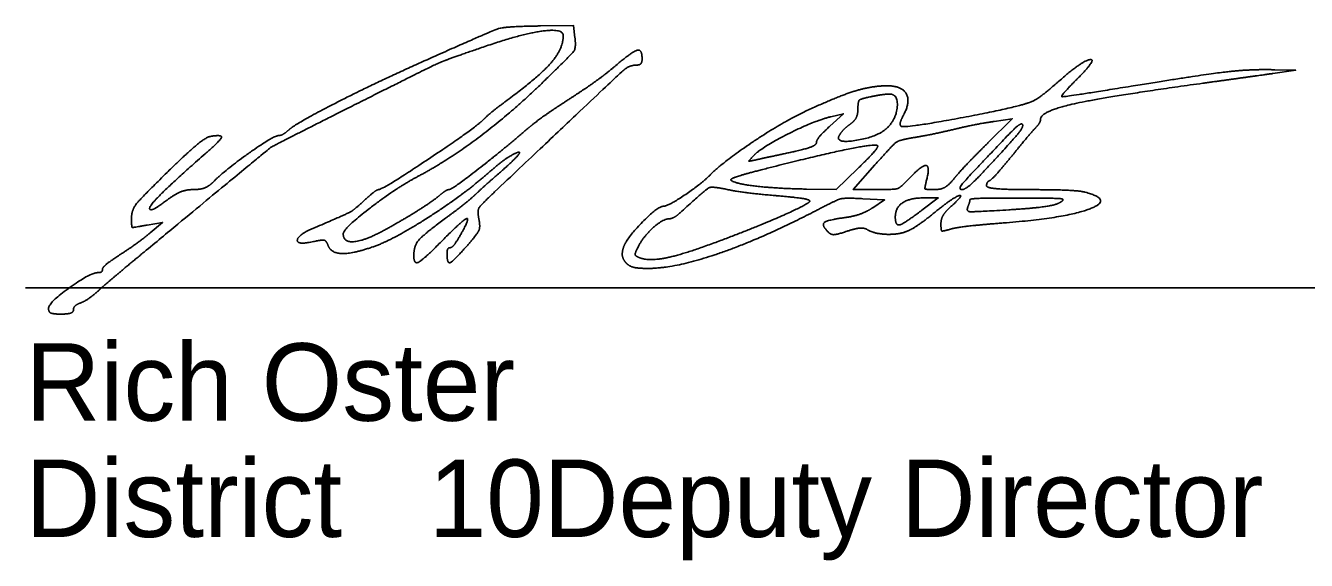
# Model space of a CAD drawing. Extents: x 6.3 to 40.3, y 9 to 31.
# Drawn here: x 30.872 to 33.187, y 17.168 to 18.134 of the extents above; entities that cross this region are included whole.
import ezdxf

# ---------------------------------------------------------------- set-up
doc = ezdxf.new("R2010")
doc.units = 0
doc.layers.add('SH_Data', color=7, linetype='Continuous')
doc.layers.add('SH_Text', color=7, linetype='Continuous')

msp = doc.modelspace()

# ---------------------------------------------------------------- linework, layer by layer
at = {"layer": 'SH_Data'}
msp.add_line((30.8725, 17.66), (34.3725, 17.66), dxfattribs=at)
at = {"layer": 'SH_Text'}
msp.add_line((30.9139, 17.6229), (30.9139, 17.6229), dxfattribs=at)
for points in [[(31.8651, 18.1121), (31.8626, 18.1339), (31.8026, 18.1333)], [(33.1264, 18.0474), (33.1676, 18.0532), (33.1299, 18.0542)], [(32.3277, 17.9693), (32.3501, 17.9746), (32.3258, 17.9524)], [(32.6227, 17.9608), (32.6553, 17.9656), (32.6114, 17.9222)], [(32.3762, 17.8757), (32.337, 17.8377), (32.2836, 17.8386)], [(32.4089, 17.8377), (32.368, 17.8377), (32.4072, 17.8822)], [(32.3855, 17.8212), (32.4247, 17.8189), (32.4033, 17.8049)], [(32.4964, 17.8227), (32.5216, 17.8227), (32.4921, 17.8004)], [(31.092, 17.7735), (31.1201, 17.7784), (31.0976, 17.7596)]]:
    msp.add_lwpolyline(points, dxfattribs=at)
for points in [[(31.8026, 18.1333), (31.7402, 18.1326), (31.7137, 18.1243), (31.5776, 18.0632)], [(31.7051, 18.0972), (31.7692, 18.1191), (31.8439, 18.1291), (31.8439, 18.1158)], [(31.8439, 18.1158), (31.8439, 18.0918), (31.7989, 18.0404), (31.7397, 17.9969)], [(31.8051, 18.0296), (31.8591, 18.082), (31.8673, 18.0933), (31.8651, 18.1121)], [(31.4951, 18.0049), (31.6073, 18.0613), (31.6329, 18.0725), (31.7051, 18.0972)], [(31.9864, 18.0739), (31.9864, 18.0919), (31.9688, 18.0871), (31.9371, 18.0603)], [(31.5776, 18.0632), (31.4974, 18.0272), (31.3616, 17.9576), (31.3483, 17.9457)], [(31.72, 17.8335), (31.9414, 18.0431), (31.9634, 18.0627), (31.977, 18.0627)], [(31.9371, 18.0603), (31.9209, 18.0465), (31.884, 18.0201), (31.8551, 18.0014)], [(31.977, 18.0627), (31.9822, 18.0627), (31.9864, 18.0677), (31.9864, 18.0739)], [(32.7732, 18.0383), (32.81, 18.0751), (32.7805, 18.0698), (32.7375, 18.0318)], [(33.1299, 18.0542), (33.0855, 18.0554), (33.0016, 18.0457), (32.8699, 18.0244)], [(31.5818, 17.8617), (31.6355, 17.8901), (31.7502, 17.9763), (31.8051, 18.0296)], [(32.7375, 18.0318), (32.7183, 18.0149), (32.6959, 17.9985), (32.6876, 17.9955)], [(32.7064, 17.9648), (32.7064, 17.9792), (32.829, 18.0064), (32.9997, 18.0298)], [(32.8699, 18.0244), (32.7495, 18.0048), (32.7409, 18.0061), (32.7732, 18.0383)], [(32.9997, 18.0298), (33.0467, 18.0363), (33.1037, 18.0442), (33.1264, 18.0474)], [(31.0864, 17.7247), (31.311, 17.9107), (31.3205, 17.9173), (31.4951, 18.0049)], [(32.429, 18.0252), (32.4015, 18.0252), (32.3397, 18.006), (32.2842, 17.9804)], [(32.3764, 17.9834), (32.3764, 17.9969), (32.3817, 18.0019), (32.3998, 18.0055)], [(32.3998, 18.0055), (32.4127, 18.0081), (32.4279, 18.0102), (32.4336, 18.0102)], [(32.4591, 17.973), (32.4718, 17.9969), (32.4555, 18.0252), (32.429, 18.0252)], [(32.4336, 18.0102), (32.4486, 18.0102), (32.4466, 17.9674), (32.4308, 17.9507)], [(31.7397, 17.9969), (31.7248, 17.986), (31.7067, 17.9711), (31.6994, 17.9638)], [(31.8551, 18.0014), (31.8263, 17.9828), (31.7925, 17.9588), (31.7801, 17.9482)], [(32.3628, 17.9562), (32.3703, 17.9616), (32.3764, 17.9739), (32.3764, 17.9834)], [(32.6876, 17.9955), (32.6603, 17.9854), (32.4586, 17.948), (32.4543, 17.9522)], [(31.6994, 17.9638), (31.6846, 17.949), (31.5178, 17.8377), (31.5105, 17.8377)], [(32.2842, 17.9804), (32.2422, 17.9609), (32.1337, 17.8886), (32.108, 17.8628)], [(32.1889, 17.8999), (32.2033, 17.9148), (32.2984, 17.9624), (32.3277, 17.9693)], [(32.4543, 17.9522), (32.452, 17.9545), (32.4542, 17.9639), (32.4591, 17.973)], [(32.5489, 17.9463), (32.5716, 17.9517), (32.6048, 17.9582), (32.6227, 17.9608)], [(32.697, 17.9488), (32.7022, 17.9543), (32.7064, 17.9615), (32.7064, 17.9648)], [(31.3483, 17.9457), (31.3418, 17.9399), (31.3332, 17.9352), (31.3292, 17.9352)], [(31.7801, 17.9482), (31.7355, 17.9098), (31.6428, 17.8377), (31.6381, 17.8377)], [(32.3258, 17.9524), (32.3124, 17.9401), (32.3014, 17.9267), (32.3014, 17.9226)], [(32.4308, 17.9507), (32.4144, 17.9334), (32.3334, 17.92), (32.3431, 17.9362)], [(32.3431, 17.9362), (32.3465, 17.9418), (32.3553, 17.9508), (32.3628, 17.9562)], [(32.477, 17.9316), (32.4939, 17.9343), (32.5262, 17.9409), (32.5489, 17.9463)], [(32.5643, 17.8377), (32.5564, 17.8377), (32.5778, 17.8629), (32.6488, 17.9371)], [(32.6734, 17.9557), (32.6769, 17.9522), (32.653, 17.9232), (32.6004, 17.8669)], [(32.6488, 17.9371), (32.6604, 17.9493), (32.6715, 17.9576), (32.6734, 17.9557)], [(32.6539, 17.8977), (32.6724, 17.9204), (32.6918, 17.9434), (32.697, 17.9488)], [(31.2067, 17.9338), (31.1987, 17.9325), (31.1633, 17.9031), (31.128, 17.8686)], [(31.197, 17.9023), (31.2247, 17.9264), (31.2281, 17.9373), (31.2067, 17.9338)], [(31.3292, 17.9352), (31.3205, 17.9352), (31.2308, 17.8714), (31.2117, 17.8516)], [(32.2017, 17.8733), (32.2985, 17.8982), (32.408, 17.921), (32.4118, 17.9172)], [(32.3014, 17.9226), (32.3014, 17.9184), (32.282, 17.9109), (32.2583, 17.9057)], [(32.4118, 17.9172), (32.4138, 17.9153), (32.3977, 17.8966), (32.3762, 17.8757)], [(32.4072, 17.8822), (32.4396, 17.919), (32.4518, 17.9276), (32.477, 17.9316)], [(32.6114, 17.9222), (32.5874, 17.8984), (32.5601, 17.8696), (32.5508, 17.8583)], [(31.097, 17.8021), (31.0933, 17.8057), (31.1402, 17.8527), (31.197, 17.9023)], [(31.7089, 17.8679), (31.7233, 17.8806), (31.7415, 17.8945), (31.7492, 17.8988)], [(31.7492, 17.8988), (31.7699, 17.9104), (31.7573, 17.8927), (31.7248, 17.8644)], [(32.1964, 17.8923), (32.1796, 17.8887), (32.1788, 17.8895), (32.1889, 17.8999)], [(32.2583, 17.9057), (32.2345, 17.9006), (32.2067, 17.8946), (32.1964, 17.8923)], [(32.6145, 17.8539), (32.6176, 17.8553), (32.6353, 17.875), (32.6539, 17.8977)], [(31.128, 17.8686), (31.0816, 17.8231), (31.0639, 17.8006), (31.0639, 17.7871)], [(31.4996, 17.734), (31.5367, 17.7467), (31.6632, 17.8278), (31.7089, 17.8679)], [(32.1468, 17.8548), (32.1448, 17.8567), (32.1695, 17.8651), (32.2017, 17.8733)], [(32.5008, 17.8564), (32.507, 17.8812), (32.491, 17.8811), (32.4675, 17.8563)], [(32.6004, 17.8669), (32.5854, 17.8508), (32.5691, 17.8377), (32.5643, 17.8377)], [(31.2117, 17.8516), (31.2043, 17.8439), (31.1881, 17.8377), (31.1756, 17.8377)], [(31.4464, 17.7577), (31.4464, 17.7672), (31.5422, 17.8408), (31.5818, 17.8617)], [(31.7248, 17.8644), (31.7102, 17.8518), (31.6926, 17.8359), (31.6857, 17.8292)], [(32.108, 17.8628), (32.0927, 17.8475), (32.0334, 17.8077), (32.0259, 17.8077)], [(32.2836, 17.8386), (32.2283, 17.8396), (32.1531, 17.8485), (32.1468, 17.8548)], [(32.4675, 17.8563), (32.4529, 17.8409), (32.4427, 17.8377), (32.4089, 17.8377)], [(32.515, 17.8377), (32.4986, 17.8377), (32.4967, 17.8401), (32.5008, 17.8564)], [(32.5508, 17.8583), (32.5405, 17.8457), (32.5266, 17.8377), (32.515, 17.8377)], [(32.6089, 17.8446), (32.6089, 17.8483), (32.6114, 17.8526), (32.6145, 17.8539)], [(32.6895, 17.8376), (32.6452, 17.8376), (32.6089, 17.8408), (32.6089, 17.8446)], [(31.1756, 17.8377), (31.1626, 17.8377), (31.1418, 17.8292), (31.1269, 17.8179)], [(31.5105, 17.8377), (31.5079, 17.8377), (31.4966, 17.8292), (31.4855, 17.8189)], [(31.6242, 17.8301), (31.6096, 17.8178), (31.5618, 17.7873), (31.525, 17.7667)], [(31.6381, 17.8377), (31.6354, 17.8377), (31.6292, 17.8343), (31.6242, 17.8301)], [(31.6857, 17.8292), (31.6788, 17.8225), (31.6543, 17.803), (31.6313, 17.786)], [(31.6916, 17.7839), (31.6887, 17.7992), (31.6944, 17.8093), (31.72, 17.8335)], [(32.0581, 17.7984), (32.1023, 17.8387), (32.1132, 17.8437), (32.142, 17.8375)], [(32.142, 17.8375), (32.1575, 17.8342), (32.1983, 17.8292), (32.2327, 17.8263)], [(32.2327, 17.8263), (32.2671, 17.8234), (32.2924, 17.8186), (32.2889, 17.8156)], [(32.3032, 17.801), (32.338, 17.8192), (32.3537, 17.823), (32.3855, 17.8212)], [(32.4439, 17.7878), (32.4439, 17.8051), (32.4703, 17.8227), (32.4964, 17.8227)], [(32.5174, 17.7983), (32.55, 17.8246), (32.5693, 17.8292), (32.5414, 17.804)], [(32.5789, 17.8195), (32.5789, 17.8213), (32.6185, 17.8226), (32.667, 17.8224)], [(32.6389, 17.7774), (32.7501, 17.7859), (32.8388, 17.8191), (32.7873, 17.8329)], [(32.667, 17.8224), (32.7341, 17.8223), (32.7518, 17.8203), (32.7411, 17.8141)], [(32.7873, 17.8329), (32.7779, 17.8354), (32.7339, 17.8375), (32.6895, 17.8376)], [(31.1269, 17.8179), (31.1127, 17.807), (31.0992, 17.7999), (31.097, 17.8021)], [(31.4855, 17.8189), (31.4663, 17.8011), (31.4518, 17.7931), (31.3958, 17.7693)], [(32.0259, 17.8077), (32.015, 17.8077), (31.9579, 17.7493), (31.9526, 17.7326)], [(31.997, 17.6952), (32.0466, 17.6952), (32.2059, 17.7502), (32.3032, 17.801)], [(32.0356, 17.7849), (32.04, 17.7851), (32.0501, 17.7911), (32.0581, 17.7984)], [(32.2889, 17.8156), (32.2795, 17.8075), (32.1775, 17.7637), (32.1139, 17.7403)], [(32.4033, 17.8049), (32.3915, 17.7973), (32.3687, 17.7892), (32.3527, 17.7871)], [(32.4921, 17.8004), (32.4601, 17.7762), (32.4439, 17.7719), (32.4439, 17.7878)], [(32.4701, 17.7646), (32.4784, 17.7687), (32.4997, 17.7839), (32.5174, 17.7983)], [(32.5414, 17.804), (32.5332, 17.7965), (32.5264, 17.7837), (32.5264, 17.7756)], [(32.6491, 17.8011), (32.5856, 17.7972), (32.5719, 17.7981), (32.575, 17.8063)], [(32.575, 17.8063), (32.5772, 17.8119), (32.5789, 17.8178), (32.5789, 17.8195)], [(32.7411, 17.8141), (32.7334, 17.8096), (32.692, 17.8038), (32.6491, 17.8011)], [(31.0639, 17.7871), (31.0639, 17.7697), (31.0657, 17.7688), (31.092, 17.7735)], [(31.6313, 17.786), (31.5914, 17.7566), (31.5739, 17.7359), (31.5739, 17.7182)], [(31.6238, 17.7439), (31.6622, 17.7829), (31.6763, 17.7875), (31.6579, 17.7552)], [(31.6713, 17.7375), (31.6889, 17.7576), (31.6943, 17.7698), (31.6916, 17.7839)], [(31.9799, 17.7352), (31.9896, 17.7539), (32.0239, 17.7845), (32.0356, 17.7849)], [(32.3527, 17.7871), (32.3212, 17.7828), (32.3102, 17.7734), (32.3224, 17.7612)], [(32.5264, 17.7756), (32.5264, 17.7638), (32.5297, 17.762), (32.5433, 17.7661)], [(32.5433, 17.7661), (32.5525, 17.7689), (32.5956, 17.774), (32.6389, 17.7774)], [(31.0976, 17.7596), (31.0853, 17.7492), (31.0608, 17.7315), (31.0433, 17.7202)], [(31.3958, 17.7693), (31.3645, 17.7561), (31.3624, 17.737), (31.3929, 17.7437)], [(31.525, 17.7667), (31.4879, 17.746), (31.4464, 17.7413), (31.4464, 17.7577)], [(31.6579, 17.7552), (31.6509, 17.7429), (31.6426, 17.7327), (31.6395, 17.7327)], [(32.3224, 17.7612), (32.3276, 17.756), (32.3386, 17.7564), (32.3568, 17.7624)], [(32.3568, 17.7624), (32.3715, 17.7673), (32.3875, 17.7688), (32.3922, 17.7659)], [(32.3922, 17.7659), (32.4063, 17.7572), (32.454, 17.7564), (32.4701, 17.7646)], [(31.3929, 17.7437), (31.4086, 17.7472), (31.4157, 17.7453), (31.419, 17.7368)], [(31.419, 17.7368), (31.4244, 17.7227), (31.4631, 17.7214), (31.4996, 17.734)], [(31.5739, 17.7182), (31.5739, 17.702), (31.5914, 17.711), (31.6238, 17.7439)], [(31.6339, 17.7214), (31.6339, 17.7033), (31.6457, 17.7083), (31.6713, 17.7375)], [(31.6395, 17.7327), (31.6364, 17.7327), (31.6339, 17.7276), (31.6339, 17.7214)], [(31.9526, 17.7326), (31.9499, 17.724), (31.9517, 17.7121), (31.9567, 17.7061)], [(31.9808, 17.715), (31.9737, 17.718), (31.9735, 17.7228), (31.9799, 17.7352)], [(32.1139, 17.7403), (32.0566, 17.7193), (31.9976, 17.7081), (31.9808, 17.715)], [(31.0039, 17.6549), (31.0142, 17.6643), (31.0513, 17.6957), (31.0864, 17.7247)], [(31.0433, 17.7202), (31.0257, 17.7089), (31.0114, 17.697), (31.0114, 17.6937)], [(31.9567, 17.7061), (31.9619, 17.6997), (31.9788, 17.6952), (31.997, 17.6952)], [(31.0038, 17.6877), (30.9896, 17.6877), (30.9139, 17.6331), (30.9139, 17.6229)], [(31.0114, 17.6937), (31.0114, 17.6904), (31.008, 17.6877), (31.0038, 17.6877)], [(30.972, 17.633), (30.9792, 17.6357), (30.9936, 17.6456), (31.0039, 17.6549)], [(30.9139, 17.6229), (30.9139, 17.6165), (30.9224, 17.6127), (30.9364, 17.6127)], [(30.9364, 17.6127), (30.9488, 17.6127), (30.9589, 17.6162), (30.9589, 17.6204)], [(30.9589, 17.6204), (30.9589, 17.6247), (30.9648, 17.6303), (30.972, 17.633)]]:
    msp.add_open_spline(points, degree=2, dxfattribs=at)

# ---------------------------------------------------------------- texts
for s, p in [('Rich Oster', (30.8725, 17.42)), ('District       Deputy Director', (30.8725, 17.21)), ('              10', (30.8725, 17.21))]:
    msp.add_text(s, height=0.14, dxfattribs=at).set_placement(p)

doc.saveas('drawing.dxf')
